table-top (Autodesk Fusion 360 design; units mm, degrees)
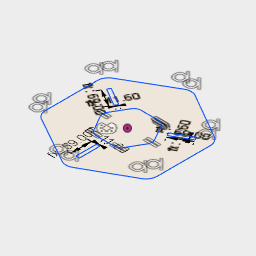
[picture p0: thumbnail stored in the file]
parameter "tabslotlength" = 69
parameter "tabslotwedth" = 11.6
sketch "Sketch1" plane through (0, 0, 0) normal (0, 1, 0) x axis (1, 0, 0)
  line L1 (-13.8108, -206.2041) -> (-170.7105, -118.4179)
  line L2 (170.7319, -123.4416) -> (22.8097, -206.2042)
  line L3 (190.4696, 88.0885) -> (190.4694, -89.7817)
  line L4 (19.3691, 208.7525) -> (171.5218, 120.9071)
  line L5 (-170.7096, 120.7534) -> (-18.2908, 208.7525)
  line L6 (-189.3069, -86.704) -> (-189.3071, 88.5416)
  line L7 (79.3857, -12.5) -> (50.5181, -62.5)
  line L8 (50.5181, 62.5) -> (79.3857, 12.5)
  line L9 (-28.8675, 75) -> (28.8675, 75)
  line L10 (-79.3857, 12.5) -> (-50.5181, 62.5)
  line L11 (-50.5181, -62.5) -> (-79.3857, -12.5)
  line L12 (28.8675, -75) -> (-28.8675, -75)
  line L13 (82.7313, 55.155) -> (142.4866, 89.6557)
  line L14 (148.2831, 79.6078) -> (142.4866, 89.6557)
  line L15 (88.5274, 45.1078) -> (148.2831, 79.6078)
  line L16 (88.5313, 45.1091) -> (82.7313, 55.155)
  line L17 (-83.3312, 54.1158) -> (-89.1312, 44.0699)
  line L18 (-83.3282, 54.1131) -> (-143.084, 88.6131)
  line L19 (-89.1312, 44.0699) -> (-148.8874, 78.5691)
  line L20 (-143.084, 88.6131) -> (-148.8874, 78.5691)
  line L21 (-5.2, -99.2249) -> (6.4, -99.2249)
  line L22 (-5.1992, -99.2209) -> (-5.1992, -168.2209)
  line L23 (6.4, -99.2249) -> (6.4008, -168.2249)
  line L24 (-5.1992, -168.2209) -> (6.4008, -168.2249)
  arc A1 centre (-28.8675, 50) radius 25 clockwise from (-50.5181, 62.5) to (-28.8675, 75)
  arc A2 centre (28.8675, 50) radius 25 clockwise from (28.8675, 75) to (50.5181, 62.5)
  arc A3 centre (57.735, 0) radius 25 clockwise from (79.3857, 12.5) to (79.3857, -12.5)
  arc A4 centre (28.8675, -50) radius 25 clockwise from (50.5181, -62.5) to (28.8675, -75)
  arc A5 centre (-28.8675, -50) radius 25 clockwise from (-28.8675, -75) to (-50.5181, -62.5)
  arc A6 centre (-57.735, 0) radius 25 clockwise from (-79.3857, -12.5) to (-79.3857, 12.5)
  arc A7 centre (152.574, 88.0885) radius 37.8956 clockwise from (171.5218, 120.9071) to (190.4696, 88.0885)
  arc A8 centre (0.5392, 176.138) radius 37.6599 clockwise from (-18.2908, 208.7525) to (19.3691, 208.7525)
  arc A9 centre (-152.1121, 88.5416) radius 37.195 clockwise from (-189.3071, 88.5416) to (-170.7096, 120.7534)
  arc A10 centre (-152.9664, -86.7039) radius 36.3405 clockwise from (-170.7105, -118.4179) to (-189.3069, -86.704)
  arc A11 centre (4.4995, -173.4782) radius 37.5 clockwise from (22.8097, -206.2042) to (-13.8108, -206.2041)
  arc A12 centre (151.8992, -89.7817) radius 38.5702 clockwise from (190.4694, -89.7817) to (170.7319, -123.4416)
  point P40 (142.4866, 89.6557)
  point P45 (148.2831, 79.6078)
  point P48 (-89.1312, 44.0699)
  point P49 (-83.3312, 54.1158)
  point P53 (-148.8874, 78.5691)
  point P58 (-5.1992, -168.2209)
  point P59 (-5.1992, -99.2209)
  point P46 (88.5274, 45.1078)
  point P56 (6.4, -99.2249)
  point P57 (-5.2, -99.2249)
  dimension "d26" distance P40 P45 = 11.6 (= "tabslotwedth")
  dimension "d32" distance P48 P49 = 11.6 (= "tabslotwedth")
  dimension "d33" distance P48 P53 = 69 (= "tabslotlength")
  dimension "d35" distance P58 P59 = 69 (= "tabslotlength")
  dimension "d36" distance P45 P46 = 69 (= "tabslotlength")
  dimension "d38" distance P56 P57 = 11.6 (= "tabslotwedth")
  dimension "d29" C-Pattern1-Angle = 360
extrude "Extrude1" new body sketch "Sketch1" profile of L1 L2 L3 L4 L5 L6 L7 L8 L9 L10 L11 L12 A1 A2 A3 A4 A5 A6 along normal blind 12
